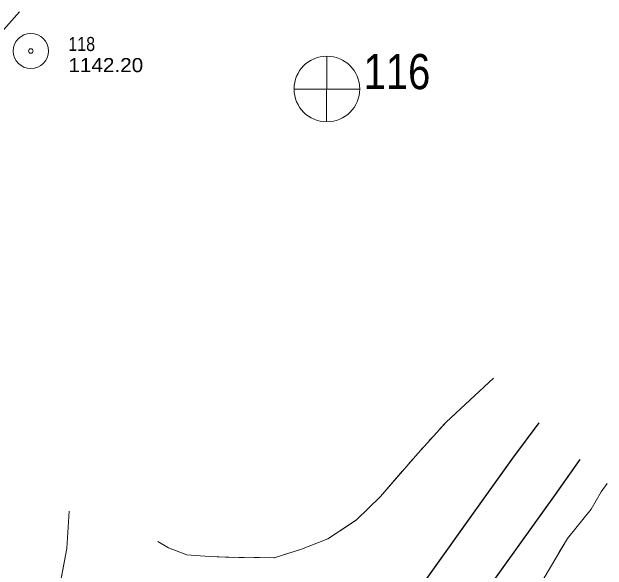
# Model space of a CAD drawing. Extents: x 300582 to 302999, y 51302 to 53600.
# Drawn here: x 301952.6 to 302206.3, y 52714.1 to 52952.1 of the extents above; entities that cross this region are included whole.
import ezdxf

# ---------------------------------------------------------------- set-up
doc = ezdxf.new("R2010")
doc.units = 0
doc.header["$LTSCALE"] = 2.4
doc.linetypes.add('LONG_DASHED', pattern=[7.5, 6, -1.5])
for name, color, linetype, lineweight in [('11', 7, 'Continuous', 25), ('19', 7, 'Continuous', 13), ('4', 7, 'Continuous', 13), ('6', 7, 'Continuous', 13)]:
    doc.layers.add(name, color=color, linetype=linetype, lineweight=lineweight)

msp = doc.modelspace()

# ---------------------------------------------------------------- linework, layer by layer
at = {"layer": '11'}
for points in [[(301790.631, 52240.188), (301811.362, 52268.952), (301834.758, 52301.902), (301855.568, 52330.847), (301876.524, 52359.962), (301895.034, 52385.599), (301914.633, 52412.642), (301935.324, 52441.425), (301962.819, 52479.632), (301985.088, 52510.301), (302013.182, 52549.479), (302035.259, 52580.267), (302059.745, 52614.271), (302085.845, 52650.072), (302106.047, 52677.908), (302129.22, 52710.139), (302151.517, 52741.398), (302166.099, 52761.911), (302177.391, 52776.932)], [(301819.169, 52239.529), (301841.265, 52270.036), (301866.294, 52304.928), (301887.003, 52333.725), (301907.637, 52362.366), (301930.485, 52394.198), (301950.448, 52421.855), (301970.827, 52449.98), (301991.782, 52478.95), (302013.431, 52509.265), (302038.019, 52543.286), (302054.779, 52566.538), (302080.08, 52602.004), (302101.586, 52631.767), (302122.935, 52661.135), (302147.043, 52694.203), (302168.841, 52724.743), (302184.37, 52746.358), (302194.801, 52761.275)]]:
    msp.add_lwpolyline(points, dxfattribs=at)
at = {"layer": '19'}
for p, q in [((302132.145, 52771.106), (302130.692, 52769.491)), ((302127.785, 52766.262), (302126.331, 52764.647)), ((302123.462, 52761.377), (302122.034, 52759.734)), ((302051.589, 52719.52), (302049.414, 52719.537)), ((302058.113, 52719.469), (302055.938, 52719.486)), ((302182.194, 52715.333), (302183.456, 52717.46))]:
    msp.add_line(p, q, dxfattribs=at)
for points in [[(302157.944, 52796.004), (302137.69, 52777.266), (302125.593, 52763.827), (302109.685, 52745.532), (302099.559, 52735.519), (302087.26, 52727.386), (302076.022, 52723.01), (302064.408, 52719.419), (302047.07, 52719.556), (302036.667, 52719.971), (302027.24, 52720.623), (302019.316, 52723.678), (302014.85, 52726.357)], [(302157.944, 52796.004), (302137.69, 52777.266), (302135.052, 52774.336)], [(302119.178, 52756.449), (302109.685, 52745.532), (302099.559, 52735.519), (302097.185, 52733.949)], [(302151.425, 52669.01), (302163.696, 52685.682), (302179.523, 52710.833), (302189.505, 52727.654), (302199.512, 52740.166), (302203.84, 52747.555), (302206.342, 52751.117)], [(302185.98, 52721.714), (302189.505, 52727.654), (302199.512, 52740.166), (302203.84, 52747.555), (302206.342, 52751.117)], [(301999.656, 52593.244), (301995.346, 52597.263), (301989.334, 52601.421), (301984.741, 52604.903), (301983.048, 52612.702), (301983.997, 52618.982), (301984.514, 52631.952), (301980.664, 52641.995), (301975.4, 52657.327), (301973.027, 52672.97), (301972.04, 52690.883), (301972.8, 52706.187), (301976.095, 52723.389), (301977.086, 52739.224)], [(301973.769, 52711.246), (301976.095, 52723.389), (301977.086, 52739.224)], [(302097.185, 52733.949), (302087.26, 52727.386), (302076.022, 52723.01), (302068.781, 52720.771)], [(302045.065, 52719.636), (302036.667, 52719.971), (302027.24, 52720.623), (302019.316, 52723.678), (302014.85, 52726.357)], [(302064.627, 52719.487), (302064.408, 52719.419), (302062.462, 52719.434)]]:
    msp.add_lwpolyline(points, dxfattribs=at)
at = {"layer": '4', "linetype": 'LONG_DASHED'}
msp.add_line((301955.887, 52952.13), (301210.553, 52140.364), dxfattribs=at)
at = {"layer": '4'}
for p, q in [((302086.836, 52933.278), (302086.771, 52905.424)), ((302072.927, 52919.248), (302100.832, 52919.235))]:
    msp.add_line(p, q, dxfattribs=at)
msp.add_circle((302086.888, 52919.256), 14, dxfattribs=at)
at = {"layer": '6'}
for radius in [7.5, 0.96]:
    msp.add_circle((301960.685, 52935.453), radius, dxfattribs=at)

# ---------------------------------------------------------------- texts
at = {"layer": '4', "width": 0.85}
msp.add_text('116', height=15, dxfattribs=at).set_placement((302102.54, 52919.186))
at = {"layer": '6'}
for s, width, p in [('118', 0.85, (301976.685, 52935.453)), ('1142.20', 1.1, (301976.685, 52926.453))]:
    msp.add_text(s, height=6, dxfattribs=dict(at, width=width)).set_placement(p)

doc.saveas('drawing.dxf')
